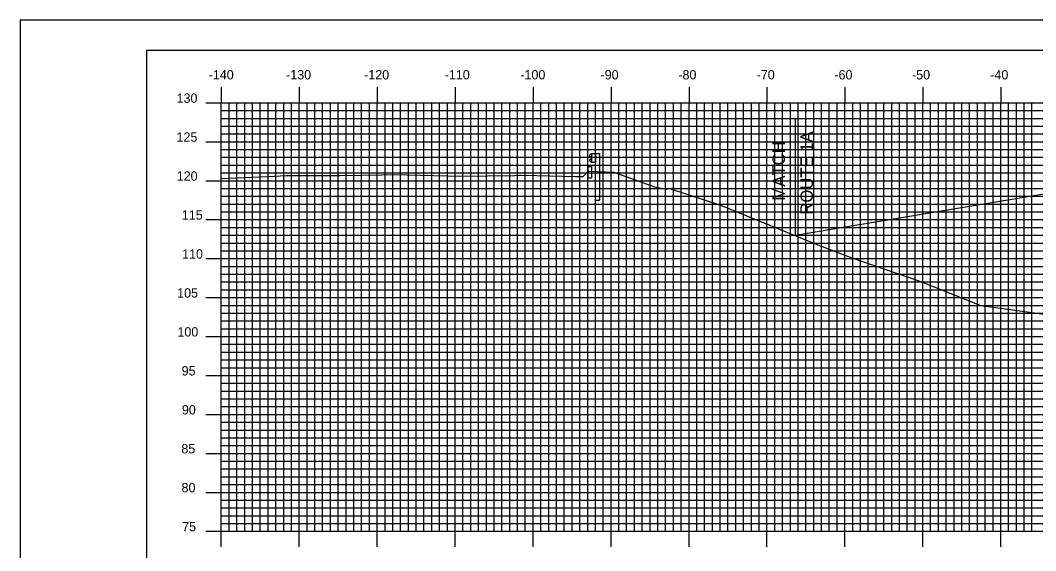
# Model space of a CAD drawing. Extents: x 856478 to 856821, y 364366 to 364586.
# Drawn here: x 856477.5 to 856607.8, y 364517.6 to 364585.7 of the extents above; entities that cross this region are included whole.
import ezdxf

# ---------------------------------------------------------------- set-up
doc = ezdxf.new("R2010")
doc.units = 0
for name, color, linetype in [('ANNOTATION', 7, 'Continuous'), ('BORDER', 7, 'Continuous'), ('D_Roadway_SlopeLines', 7, 'Continuous'), ('D_Roadway_SubGrade', 7, 'Continuous'), ('H_V ANNOTATION', 7, 'Continuous'), ('M_Roadway_Centerline', 7, 'Continuous'), ('MAJOR', 7, 'Continuous'), ('MINOR', 7, 'Continuous'), ('PLOT BOUNDARY', 7, 'Continuous'), ('S_Curb_Type_1', 7, 'Continuous'), ('S_Guardrail_Beam', 7, 'Continuous'), ('S_Roadway_Centerline', 7, 'Continuous')]:
    doc.layers.add(name, color=color, linetype=linetype)

msp = doc.modelspace()

# ---------------------------------------------------------------- linework, layer by layer
at = {"layer": 'BORDER'}
msp.add_lwpolyline([(856493.71, 364371.79), (856813.71, 364371.79), (856813.71, 364581.79), (856493.71, 364581.79)], close=True, dxfattribs=at)
at = {"layer": 'D_Roadway_SlopeLines'}
msp.add_lwpolyline([(856625.31, 364566.09), (856576.95, 364558.03)], dxfattribs=at)
at = {"layer": 'D_Roadway_SubGrade'}
msp.add_line((856576.95, 364572.99), (856576.95, 364558.03), dxfattribs=at)
at = {"layer": 'MAJOR'}
for p, q in [((856503.31, 364577.09), (856503.31, 364575.08)), ((856513.31, 364577.09), (856513.31, 364575.08)), ((856523.31, 364577.09), (856523.31, 364575.08)), ((856533.31, 364577.09), (856533.31, 364575.08)), ((856543.31, 364577.09), (856543.31, 364575.08)), ((856553.31, 364577.09), (856553.31, 364575.08)), ((856563.31, 364577.09), (856563.31, 364575.08)), ((856573.31, 364577.09), (856573.31, 364575.08)), ((856583.31, 364577.09), (856583.31, 364575.08)), ((856593.31, 364577.09), (856593.31, 364575.08)), ((856603.31, 364577.09), (856603.31, 364575.08)), ((856501.31, 364575.08), (856503.31, 364575.08)), ((856503.31, 364575.08), (856783.31, 364575.08)), ((856503.31, 364520.08), (856503.31, 364575.08)), ((856503.31, 364520.08), (856503.31, 364575.08)), ((856503.31, 364575.08), (856783.31, 364575.08)), ((856513.31, 364520.08), (856513.31, 364575.08)), ((856523.31, 364520.08), (856523.31, 364575.08)), ((856533.31, 364520.08), (856533.31, 364575.08)), ((856543.31, 364520.08), (856543.31, 364575.08)), ((856553.31, 364520.08), (856553.31, 364575.08)), ((856563.31, 364520.08), (856563.31, 364575.08)), ((856573.31, 364520.08), (856573.31, 364575.08)), ((856583.31, 364520.08), (856583.31, 364575.08)), ((856593.31, 364520.08), (856593.31, 364575.08)), ((856603.31, 364520.08), (856603.31, 364575.08)), ((856501.31, 364570.08), (856503.31, 364570.08)), ((856503.31, 364570.08), (856783.31, 364570.08)), ((856501.31, 364565.08), (856503.31, 364565.08)), ((856503.31, 364565.08), (856783.31, 364565.08)), ((856501.31, 364560.08), (856503.31, 364560.08)), ((856503.31, 364560.08), (856783.31, 364560.08)), ((856501.31, 364555.08), (856503.31, 364555.08)), ((856503.31, 364555.08), (856783.31, 364555.08)), ((856501.31, 364550.08), (856503.31, 364550.08)), ((856503.31, 364550.08), (856783.31, 364550.08)), ((856501.31, 364545.08), (856503.31, 364545.08)), ((856503.31, 364545.08), (856783.31, 364545.08)), ((856501.31, 364540.08), (856503.31, 364540.08)), ((856503.31, 364540.08), (856783.31, 364540.08)), ((856501.31, 364535.08), (856503.31, 364535.08)), ((856503.31, 364535.08), (856783.31, 364535.08)), ((856501.31, 364530.08), (856503.31, 364530.08)), ((856503.31, 364530.08), (856783.31, 364530.08)), ((856501.31, 364525.08), (856503.31, 364525.08)), ((856503.31, 364525.08), (856783.31, 364525.08)), ((856501.31, 364520.08), (856503.31, 364520.08)), ((856503.31, 364520.08), (856783.31, 364520.08)), ((856503.31, 364520.08), (856783.31, 364520.08)), ((856503.31, 364518.08), (856503.31, 364520.08)), ((856513.31, 364518.08), (856513.31, 364520.08)), ((856523.31, 364518.08), (856523.31, 364520.08)), ((856533.31, 364518.08), (856533.31, 364520.08)), ((856543.31, 364518.08), (856543.31, 364520.08)), ((856553.31, 364518.08), (856553.31, 364520.08)), ((856563.31, 364518.08), (856563.31, 364520.08)), ((856573.31, 364518.08), (856573.31, 364520.08)), ((856583.31, 364518.08), (856583.31, 364520.08)), ((856593.31, 364518.08), (856593.31, 364520.08)), ((856603.31, 364518.08), (856603.31, 364520.08))]:
    msp.add_line(p, q, dxfattribs=at)
at = {"layer": 'MINOR'}
for p, q in [((856504.31, 364520.08), (856504.31, 364575.08)), ((856505.31, 364520.08), (856505.31, 364575.08)), ((856506.31, 364520.08), (856506.31, 364575.08)), ((856507.31, 364520.08), (856507.31, 364575.08)), ((856508.31, 364520.08), (856508.31, 364575.08)), ((856509.31, 364520.08), (856509.31, 364575.08)), ((856510.31, 364520.08), (856510.31, 364575.08)), ((856511.31, 364520.08), (856511.31, 364575.08)), ((856512.31, 364520.08), (856512.31, 364575.08)), ((856514.31, 364520.08), (856514.31, 364575.08)), ((856515.31, 364520.08), (856515.31, 364575.08)), ((856516.31, 364520.08), (856516.31, 364575.08)), ((856517.31, 364520.08), (856517.31, 364575.08)), ((856518.31, 364520.08), (856518.31, 364575.08)), ((856519.31, 364520.08), (856519.31, 364575.08)), ((856520.31, 364520.08), (856520.31, 364575.08)), ((856521.31, 364520.08), (856521.31, 364575.08)), ((856522.31, 364520.08), (856522.31, 364575.08)), ((856524.31, 364520.08), (856524.31, 364575.08)), ((856525.31, 364520.08), (856525.31, 364575.08)), ((856526.31, 364520.08), (856526.31, 364575.08)), ((856527.31, 364520.08), (856527.31, 364575.08)), ((856528.31, 364520.08), (856528.31, 364575.08)), ((856529.31, 364520.08), (856529.31, 364575.08)), ((856530.31, 364520.08), (856530.31, 364575.08)), ((856531.31, 364520.08), (856531.31, 364575.08)), ((856532.31, 364520.08), (856532.31, 364575.08)), ((856534.31, 364520.08), (856534.31, 364575.08)), ((856535.31, 364520.08), (856535.31, 364575.08)), ((856536.31, 364520.08), (856536.31, 364575.08)), ((856537.31, 364520.08), (856537.31, 364575.08)), ((856538.31, 364520.08), (856538.31, 364575.08)), ((856539.31, 364520.08), (856539.31, 364575.08)), ((856540.31, 364520.08), (856540.31, 364575.08)), ((856541.31, 364520.08), (856541.31, 364575.08)), ((856542.31, 364520.08), (856542.31, 364575.08)), ((856544.31, 364520.08), (856544.31, 364575.08)), ((856545.31, 364520.08), (856545.31, 364575.08)), ((856546.31, 364520.08), (856546.31, 364575.08)), ((856547.31, 364520.08), (856547.31, 364575.08)), ((856548.31, 364520.08), (856548.31, 364575.08)), ((856549.31, 364520.08), (856549.31, 364575.08)), ((856550.31, 364520.08), (856550.31, 364575.08)), ((856551.31, 364520.08), (856551.31, 364575.08)), ((856552.31, 364520.08), (856552.31, 364575.08)), ((856554.31, 364520.08), (856554.31, 364575.08)), ((856555.31, 364520.08), (856555.31, 364575.08)), ((856556.31, 364520.08), (856556.31, 364575.08)), ((856557.31, 364520.08), (856557.31, 364575.08)), ((856558.31, 364520.08), (856558.31, 364575.08)), ((856559.31, 364520.08), (856559.31, 364575.08)), ((856560.31, 364520.08), (856560.31, 364575.08)), ((856561.31, 364520.08), (856561.31, 364575.08)), ((856562.31, 364520.08), (856562.31, 364575.08)), ((856564.31, 364520.08), (856564.31, 364575.08)), ((856565.31, 364520.08), (856565.31, 364575.08)), ((856566.31, 364520.08), (856566.31, 364575.08)), ((856567.31, 364520.08), (856567.31, 364575.08)), ((856568.31, 364520.08), (856568.31, 364575.08)), ((856569.31, 364520.08), (856569.31, 364575.08)), ((856570.31, 364520.08), (856570.31, 364575.08)), ((856571.31, 364520.08), (856571.31, 364575.08)), ((856572.31, 364520.08), (856572.31, 364575.08)), ((856574.31, 364520.08), (856574.31, 364575.08)), ((856575.31, 364520.08), (856575.31, 364575.08)), ((856576.31, 364520.08), (856576.31, 364575.08)), ((856577.31, 364520.08), (856577.31, 364575.08)), ((856578.31, 364520.08), (856578.31, 364575.08)), ((856579.31, 364520.08), (856579.31, 364575.08)), ((856580.31, 364520.08), (856580.31, 364575.08)), ((856581.31, 364520.08), (856581.31, 364575.08)), ((856582.31, 364520.08), (856582.31, 364575.08)), ((856584.31, 364520.08), (856584.31, 364575.08)), ((856585.31, 364520.08), (856585.31, 364575.08)), ((856586.31, 364520.08), (856586.31, 364575.08)), ((856587.31, 364520.08), (856587.31, 364575.08)), ((856588.31, 364520.08), (856588.31, 364575.08)), ((856589.31, 364520.08), (856589.31, 364575.08)), ((856590.31, 364520.08), (856590.31, 364575.08)), ((856591.31, 364520.08), (856591.31, 364575.08)), ((856592.31, 364520.08), (856592.31, 364575.08)), ((856594.31, 364520.08), (856594.31, 364575.08)), ((856595.31, 364520.08), (856595.31, 364575.08)), ((856596.31, 364520.08), (856596.31, 364575.08)), ((856597.31, 364520.08), (856597.31, 364575.08)), ((856598.31, 364520.08), (856598.31, 364575.08)), ((856599.31, 364520.08), (856599.31, 364575.08)), ((856600.31, 364520.08), (856600.31, 364575.08)), ((856601.31, 364520.08), (856601.31, 364575.08)), ((856602.31, 364520.08), (856602.31, 364575.08)), ((856604.31, 364520.08), (856604.31, 364575.08)), ((856605.31, 364520.08), (856605.31, 364575.08)), ((856606.31, 364520.08), (856606.31, 364575.08)), ((856607.31, 364520.08), (856607.31, 364575.08)), ((856503.31, 364574.08), (856783.31, 364574.08)), ((856503.31, 364574.08), (856505.31, 364574.08)), ((856503.31, 364573.08), (856783.31, 364573.08)), ((856503.31, 364573.08), (856505.31, 364573.08)), ((856503.31, 364572.08), (856783.31, 364572.08)), ((856503.31, 364572.08), (856505.31, 364572.08)), ((856503.31, 364571.08), (856783.31, 364571.08)), ((856503.31, 364571.08), (856505.31, 364571.08)), ((856503.31, 364569.08), (856783.31, 364569.08)), ((856503.31, 364569.08), (856505.31, 364569.08)), ((856503.31, 364568.08), (856783.31, 364568.08)), ((856503.31, 364568.08), (856505.31, 364568.08)), ((856503.31, 364567.08), (856783.31, 364567.08)), ((856503.31, 364567.08), (856505.31, 364567.08)), ((856503.31, 364566.08), (856783.31, 364566.08)), ((856503.31, 364566.08), (856505.31, 364566.08)), ((856503.31, 364564.08), (856783.31, 364564.08)), ((856503.31, 364564.08), (856505.31, 364564.08)), ((856503.31, 364563.08), (856783.31, 364563.08)), ((856503.31, 364563.08), (856505.31, 364563.08)), ((856503.31, 364562.08), (856783.31, 364562.08)), ((856503.31, 364562.08), (856505.31, 364562.08)), ((856503.31, 364561.08), (856783.31, 364561.08)), ((856503.31, 364561.08), (856505.31, 364561.08)), ((856503.31, 364559.08), (856783.31, 364559.08)), ((856503.31, 364559.08), (856505.31, 364559.08)), ((856503.31, 364558.08), (856783.31, 364558.08)), ((856503.31, 364558.08), (856505.31, 364558.08)), ((856503.31, 364557.08), (856783.31, 364557.08)), ((856503.31, 364557.08), (856505.31, 364557.08)), ((856503.31, 364556.08), (856783.31, 364556.08)), ((856503.31, 364556.08), (856505.31, 364556.08)), ((856503.31, 364554.08), (856783.31, 364554.08)), ((856503.31, 364554.08), (856505.31, 364554.08)), ((856503.31, 364553.08), (856783.31, 364553.08)), ((856503.31, 364553.08), (856505.31, 364553.08)), ((856503.31, 364552.08), (856783.31, 364552.08)), ((856503.31, 364552.08), (856505.31, 364552.08)), ((856503.31, 364551.08), (856783.31, 364551.08)), ((856503.31, 364551.08), (856505.31, 364551.08)), ((856503.31, 364549.08), (856783.31, 364549.08)), ((856503.31, 364549.08), (856505.31, 364549.08)), ((856503.31, 364548.08), (856783.31, 364548.08)), ((856503.31, 364548.08), (856505.31, 364548.08)), ((856503.31, 364547.08), (856783.31, 364547.08)), ((856503.31, 364547.08), (856505.31, 364547.08)), ((856503.31, 364546.08), (856783.31, 364546.08)), ((856503.31, 364546.08), (856505.31, 364546.08)), ((856503.31, 364544.08), (856783.31, 364544.08)), ((856503.31, 364544.08), (856505.31, 364544.08)), ((856503.31, 364543.08), (856783.31, 364543.08)), ((856503.31, 364543.08), (856505.31, 364543.08)), ((856503.31, 364542.08), (856783.31, 364542.08)), ((856503.31, 364542.08), (856505.31, 364542.08)), ((856503.31, 364541.08), (856783.31, 364541.08)), ((856503.31, 364541.08), (856505.31, 364541.08)), ((856503.31, 364539.08), (856783.31, 364539.08)), ((856503.31, 364539.08), (856505.31, 364539.08)), ((856503.31, 364538.08), (856783.31, 364538.08)), ((856503.31, 364538.08), (856505.31, 364538.08)), ((856503.31, 364537.08), (856783.31, 364537.08)), ((856503.31, 364537.08), (856505.31, 364537.08)), ((856503.31, 364536.08), (856783.31, 364536.08)), ((856503.31, 364536.08), (856505.31, 364536.08)), ((856503.31, 364534.08), (856783.31, 364534.08)), ((856503.31, 364534.08), (856505.31, 364534.08)), ((856503.31, 364533.08), (856783.31, 364533.08)), ((856503.31, 364533.08), (856505.31, 364533.08)), ((856503.31, 364532.08), (856783.31, 364532.08)), ((856503.31, 364532.08), (856505.31, 364532.08)), ((856503.31, 364531.08), (856783.31, 364531.08)), ((856503.31, 364531.08), (856505.31, 364531.08)), ((856503.31, 364529.08), (856783.31, 364529.08)), ((856503.31, 364529.08), (856505.31, 364529.08)), ((856503.31, 364528.08), (856783.31, 364528.08)), ((856503.31, 364528.08), (856505.31, 364528.08)), ((856503.31, 364527.08), (856783.31, 364527.08)), ((856503.31, 364527.08), (856505.31, 364527.08)), ((856503.31, 364526.08), (856783.31, 364526.08)), ((856503.31, 364526.08), (856505.31, 364526.08)), ((856503.31, 364524.08), (856783.31, 364524.08)), ((856503.31, 364524.08), (856505.31, 364524.08)), ((856503.31, 364523.08), (856783.31, 364523.08)), ((856503.31, 364523.08), (856505.31, 364523.08)), ((856503.31, 364522.08), (856783.31, 364522.08)), ((856503.31, 364522.08), (856505.31, 364522.08)), ((856503.31, 364521.08), (856783.31, 364521.08)), ((856503.31, 364521.08), (856505.31, 364521.08))]:
    msp.add_line(p, q, dxfattribs=at)
at = {"layer": 'PLOT BOUNDARY'}
msp.add_lwpolyline([(856477.52, 364365.67), (856817.52, 364365.67), (856817.52, 364585.67), (856477.52, 364585.67)], close=True, dxfattribs=at)
at = {"layer": 'S_Curb_Type_1'}
msp.add_lwpolyline([(856550.38, 364566.9), (856550.79, 364566.9), (856550.79, 364565.4), (856550.38, 364565.4)], close=True, dxfattribs=at)
msp.add_lwpolyline([(856550.38, 364566.9), (856550.79, 364566.9), (856550.79, 364565.4), (856550.38, 364565.4)], close=True, dxfattribs=at)
at = {"layer": 'S_Guardrail_Beam'}
for p, q in [((856550.73, 364568.49), (856550.59, 364568.39)), ((856550.73, 364568.49), (856550.59, 364568.39)), ((856550.83, 364568.51), (856550.75, 364568.49)), ((856550.83, 364568.51), (856550.75, 364568.49)), ((856550.83, 364568.58), (856551.32, 364568.58)), ((856550.83, 364567.41), (856550.83, 364568.58)), ((856550.83, 364568.58), (856551.32, 364568.58)), ((856550.83, 364567.41), (856550.83, 364568.58)), ((856551.32, 364568.58), (856551.81, 364568.58)), ((856551.32, 364568.58), (856551.32, 364567.41)), ((856551.32, 364568.58), (856551.81, 364568.58)), ((856551.32, 364568.58), (856551.32, 364567.41)), ((856551.81, 364568.58), (856551.81, 364562.58)), ((856551.81, 364568.58), (856551.81, 364562.58)), ((856550.59, 364568.24), (856550.79, 364568.11)), ((856550.59, 364568.24), (856550.79, 364568.11)), ((856550.79, 364567.89), (856550.59, 364567.75)), ((856550.79, 364567.89), (856550.59, 364567.75)), ((856550.59, 364567.61), (856550.73, 364567.51)), ((856550.59, 364567.61), (856550.73, 364567.51)), ((856550.75, 364567.5), (856550.83, 364567.49)), ((856550.75, 364567.5), (856550.83, 364567.49)), ((856550.82, 364568.04), (856550.82, 364567.95)), ((856550.82, 364568.04), (856550.82, 364567.95)), ((856551.32, 364567.41), (856550.83, 364567.41)), ((856551.32, 364567.41), (856550.83, 364567.41)), ((856551.32, 364562.58), (856551.32, 364567.41)), ((856551.32, 364562.58), (856551.32, 364567.41)), ((856551.32, 364562.58), (856551.81, 364562.58)), ((856551.32, 364562.58), (856551.81, 364562.58))]:
    msp.add_line(p, q, dxfattribs=at)
for centre, major_axis, start_param, end_param in [((856550.76, 364568.45), (-0.0417, 0), 4.886922, 5.323254), ((856550.76, 364568.45), (-0.0417, 0), 4.886922, 5.323254), ((856550.64, 364568.32), (-0.0877, 0), 5.323254, 7.243116), ((856550.64, 364568.32), (-0.0877, 0), 5.323254, 7.243116), ((856550.64, 364567.68), (-0.0877, 0), 5.323254, 7.243116), ((856550.64, 364567.68), (-0.0877, 0), 5.323254, 7.243116), ((856550.76, 364567.54), (-0.0417, 0), 0.959931, 1.396263), ((856550.76, 364567.54), (-0.0417, 0), 0.959931, 1.396263), ((856550.74, 364568.04), (0.0789, 0), 0, 0.959931), ((856550.74, 364568.04), (0.0789, 0), 0, 0.959931), ((856550.74, 364567.95), (0.0789, 0), 5.323254, 6.283185), ((856550.74, 364567.95), (0.0789, 0), 5.323254, 6.283185)]:
    msp.add_ellipse(centre, major_axis=major_axis, ratio=0.995501, start_param=start_param, end_param=end_param, dxfattribs=at)
at = {"layer": 'S_Roadway_Centerline'}
msp.add_lwpolyline([(856503.31, 364565.35), (856509.32, 364565.62), (856511.62, 364565.74), (856511.81, 364565.74), (856515.99, 364565.74), (856518.25, 364565.74), (856518.26, 364565.74), (856518.56, 364565.74), (856526.56, 364565.89), (856527.11, 364565.85), (856534, 364565.67), (856540.93, 364565.76), (856541.5, 364565.78), (856541.72, 364565.77), (856543.77, 364565.73), (856548.73, 364565.61), (856549.71, 364565.6), (856549.75, 364565.6), (856550.33, 364566.28), (856550.38, 364566.32), (856550.49, 364566.31), (856553.67, 364566.18), (856558.89, 364564.31), (856560.44, 364563.98), (856560.68, 364564.14), (856567.37, 364561.93), (856579.63, 364556.94), (856584.2, 364555.2), (856592.93, 364552.19), (856600.75, 364549.07), (856609.18, 364547.9)], dxfattribs=at)

# ---------------------------------------------------------------- texts
at = {"layer": 'ANNOTATION'}
for s, p in [('ROUTE 1A', (856579.21, 364560.72)), ('MATCH', (856575.61, 364562.53))]:
    msp.add_text(s, height=1.6, rotation=90, dxfattribs=at).set_placement(p)
at = {"layer": 'H_V ANNOTATION'}
for s, p in [('-140', (856501.69, 364578.08)), ('-130', (856511.62, 364578.08)), ('-120', (856521.63, 364578.08)), ('-110', (856531.97, 364578.08)), ('-100', (856541.67, 364578.08)), ('-90', (856551.96, 364578.08)), ('-80', (856561.94, 364578.08)), ('-70', (856571.99, 364578.08)), ('-60', (856581.96, 364578.08)), ('-50', (856591.92, 364578.08)), ('-40', (856601.96, 364578.08)), ('130', (856497.57, 364575.08)), ('125', (856497.56, 364570.08)), ('120', (856497.59, 364565.08)), ('115', (856498.24, 364560.08)), ('110', (856498.28, 364555.08)), ('105', (856497.64, 364550.08)), ('100', (856497.68, 364545.08)), ('95', (856498.22, 364540.08)), ('90', (856498.25, 364535.08)), ('85', (856498.18, 364530.08)), ('80', (856498.21, 364525.08)), ('75', (856498.29, 364520.08))]:
    msp.add_text(s, height=1.2, dxfattribs=at).set_placement(p)
at = {"layer": 'M_Roadway_Centerline'}
for s, p in [('C', (856518.25, 364565.74)), ('L', (856518.26, 364565.73))]:
    msp.add_text(s, height=0.0146, dxfattribs=at).set_placement(p)
at = {"layer": 'MAJOR'}
msp.add_text('-', height=0.012, dxfattribs=at).set_placement((856503.3, 364520.08))

doc.saveas('drawing.dxf')
